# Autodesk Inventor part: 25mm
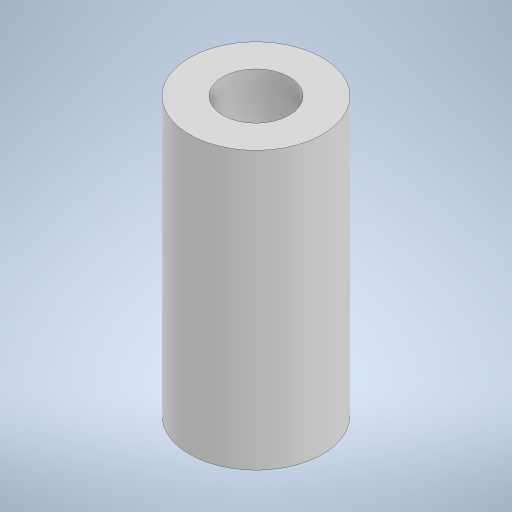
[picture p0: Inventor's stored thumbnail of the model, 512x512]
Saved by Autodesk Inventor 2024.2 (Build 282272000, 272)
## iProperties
Created: 2024-05
Part Number: 25mm
Material: Generic
Document SubType Name: Modeling
Designer: Karsten
Density: 1 g/cm^3
Appearance: Default
Author: Karsten
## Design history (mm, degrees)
sketch "Sketch1"
  geometry: C1 r 3 at (0, 0); C2 r 6 at (0, 0); 1 further point
  constraints: 2 centre point, 2 coincident
  dimensions: "d0" = 6 diameter of C1; "d1" = 12 diameter of C2
extrude "Extrusion1" new body sketch "Sketch1" distance "d2" = 25; taper "d3" = 0 deg
body "Solid1"
